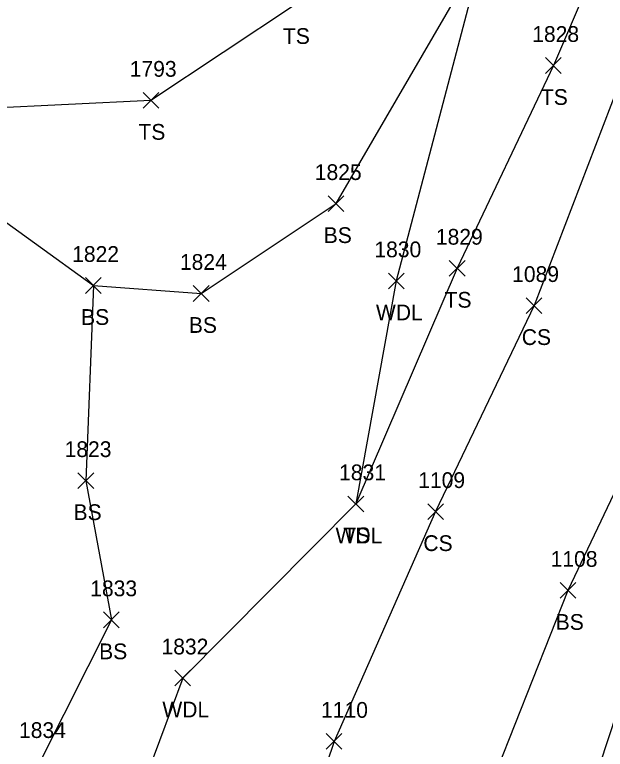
# Model space of a CAD drawing. Extents: x 1551995 to 1555700, y 777276 to 783130.
# Drawn here: x 1554843.1 to 1554918, y 778118.1 to 778211.4 of the extents above; entities that cross this region are included whole.
import ezdxf

# ---------------------------------------------------------------- set-up
doc = ezdxf.new("R2010")
doc.units = 0
for name, color, linetype in [('L_A', 7, 'Continuous'), ('L_I', 7, 'Continuous'), ('L_TIC', 7, 'Continuous'), ('LAWA', 7, 'Continuous'), ('LELB', 7, 'Continuous')]:
    doc.layers.add(name, color=color, linetype=linetype)

msp = doc.modelspace()

# ---------------------------------------------------------------- linework, layer by layer
at = {"layer": 'L_TIC'}
for points in [[(1554910.425, 778203.896), (1554912.425, 778205.896)], [(1554912.425, 778203.896), (1554910.425, 778205.896)], [(1554859.354, 778199.473), (1554861.354, 778201.473)], [(1554861.354, 778199.473), (1554859.354, 778201.473)], [(1554882.836, 778186.364), (1554884.836, 778188.364)], [(1554884.836, 778186.364), (1554882.836, 778188.364)], [(1554898.206, 778178.156), (1554900.206, 778180.156)], [(1554900.206, 778178.156), (1554898.206, 778180.156)], [(1554852.047, 778175.969), (1554854.047, 778177.969)], [(1554854.047, 778175.969), (1554852.047, 778177.969)], [(1554852.047, 778175.969), (1554854.047, 778177.969)], [(1554854.047, 778175.969), (1554852.047, 778177.969)], [(1554890.484, 778176.555), (1554892.484, 778178.555)], [(1554892.484, 778176.555), (1554890.484, 778178.555)], [(1554865.72, 778174.958), (1554867.72, 778176.958)], [(1554867.72, 778174.958), (1554865.72, 778176.958)], [(1554907.964, 778173.418), (1554909.964, 778175.418)], [(1554909.964, 778173.418), (1554907.964, 778175.418)], [(1554851.09, 778151.192), (1554853.09, 778153.192)], [(1554853.09, 778151.192), (1554851.09, 778153.192)], [(1554885.356, 778148.248), (1554887.356, 778150.248)], [(1554887.356, 778148.248), (1554885.356, 778150.248)], [(1554885.356, 778148.248), (1554887.356, 778150.248)], [(1554887.356, 778148.248), (1554885.356, 778150.248)], [(1554895.479, 778147.261), (1554897.479, 778149.261)], [(1554897.479, 778147.261), (1554895.479, 778149.261)], [(1554912.271, 778137.258), (1554914.271, 778139.258)], [(1554914.271, 778137.258), (1554912.271, 778139.258)], [(1554854.338, 778133.523), (1554856.338, 778135.523)], [(1554856.338, 778133.523), (1554854.338, 778135.523)], [(1554863.384, 778126.135), (1554865.384, 778128.135)], [(1554865.384, 778126.135), (1554863.384, 778128.135)], [(1554882.583, 778118.092), (1554884.583, 778120.092)], [(1554884.583, 778118.092), (1554882.583, 778120.092)]]:
    msp.add_lwpolyline(points, dxfattribs=at)
at = {"layer": 'LAWA'}
for points in [[(1554935.431, 778396.621), (1554932.573, 778365.344), (1554927.798, 778334.859), (1554903.785, 778283.497), (1554902.475, 778219.435), (1554891.484, 778177.555), (1554886.356, 778149.248), (1554864.384, 778127.135), (1554855.538, 778103.274), (1554855.616, 778088.162), (1554832.422, 778095.389), (1554813.643, 778080.716)], [(1555000.959, 778294.871), (1554977.329, 778249.83), (1554953.65, 778203.431), (1554934.128, 778158.372), (1554921.739, 778129.694), (1554915.004, 778109.124), (1554905.48, 778082.177), (1554899.619, 778064.005), (1554889.875, 778042.086), (1554882.71, 778000.014), (1554871.693, 777971.466), (1554868.372, 777961.536), (1554861.965, 777920.449), (1554858.528, 777878.75), (1554855.375, 777850.348), (1554848.666, 777827.396), (1554836.715, 777779.634)]]:
    msp.add_lwpolyline(points, dxfattribs=at)
at = {"layer": 'LELB'}
for points in [[(1554951.121, 778362.296), (1554943.389, 778319.892), (1554928.058, 778285.607), (1554924.889, 778236.389), (1554911.425, 778204.896), (1554899.206, 778179.156), (1554886.356, 778149.248)], [(1554968.281, 778312.044), (1554950.001, 778266.534), (1554926.493, 778220.19), (1554908.964, 778174.418), (1554896.479, 778148.261), (1554883.583, 778119.092), (1554877.326, 778100.58), (1554861.426, 778063.061), (1554849.037, 778068.426), (1554838.512, 778079.969)], [(1554991.435, 778299.233), (1554965.179, 778257.458), (1554942.555, 778207.52), (1554927.413, 778168.062), (1554913.271, 778138.258), (1554902.026, 778109.912)], [(1554888.102, 778278.073), (1554881.602, 778269.104), (1554881.406, 778246.042), (1554876.741, 778227.33), (1554877.836, 778223.947), (1554878.695, 778212.64), (1554860.354, 778200.473), (1554839.385, 778199.43), (1554828.217, 778212.966), (1554822.863, 778217.911), (1554830.877, 778220.876), (1554825.413, 778230.382), (1554822.915, 778242.559), (1554824.365, 778250.862)], [(1554800.406, 778253.928), (1554822.718, 778192.195), (1554838.053, 778187.794), (1554853.047, 778176.969), (1554852.09, 778152.192), (1554855.338, 778134.523), (1554846.304, 778116.527), (1554831.672, 778103.381), (1554813.355, 778099.277)], [(1554853.047, 778176.969), (1554866.72, 778175.958), (1554883.836, 778187.364), (1554902.475, 778219.435)]]:
    msp.add_lwpolyline(points, dxfattribs=at)

# ---------------------------------------------------------------- texts
at = {"layer": 'L_A'}
for s, p in [('TS', (1554877.104, 778207.64)), ('TS', (1554909.834, 778199.896)), ('TS', (1554858.764, 778195.473)), ('BS', (1554882.277, 778182.364)), ('TS', (1554897.616, 778174.156)), ('WDL', (1554888.901, 778172.555)), ('BS', (1554851.488, 778171.969)), ('BS', (1554851.488, 778171.969)), ('BS', (1554865.161, 778170.958)), ('CS', (1554907.405, 778169.418)), ('BS', (1554850.531, 778147.192)), ('WDL', (1554883.773, 778144.248)), ('TS', (1554884.765, 778144.248)), ('CS', (1554894.92, 778143.261)), ('BS', (1554911.712, 778133.258)), ('BS', (1554853.779, 778129.523)), ('WDL', (1554861.801, 778122.135))]:
    msp.add_text(s, height=2, dxfattribs=at).set_placement(p)
at = {"layer": 'L_I'}
for s, p in [('1828', (1554908.732, 778207.896)), ('1793', (1554857.661, 778203.473)), ('1825', (1554881.143, 778190.364)), ('1829', (1554896.506, 778182.156)), ('1822', (1554850.355, 778179.969)), ('1822', (1554850.355, 778179.969)), ('1830', (1554888.704, 778180.555)), ('1824', (1554864.027, 778178.958)), ('1089', (1554906.185, 778177.418)), ('1823', (1554849.397, 778155.192)), ('1831', (1554884.23, 778152.248)), ('1831', (1554884.23, 778152.248)), ('1109', (1554894.267, 778151.261)), ('1108', (1554911.066, 778141.258)), ('1833', (1554852.645, 778137.523)), ('1832', (1554861.691, 778130.135)), ('1110', (1554881.937, 778122.092)), ('1834', (1554843.611, 778119.527))]:
    msp.add_text(s, height=2, dxfattribs=at).set_placement(p)

doc.saveas('drawing.dxf')
